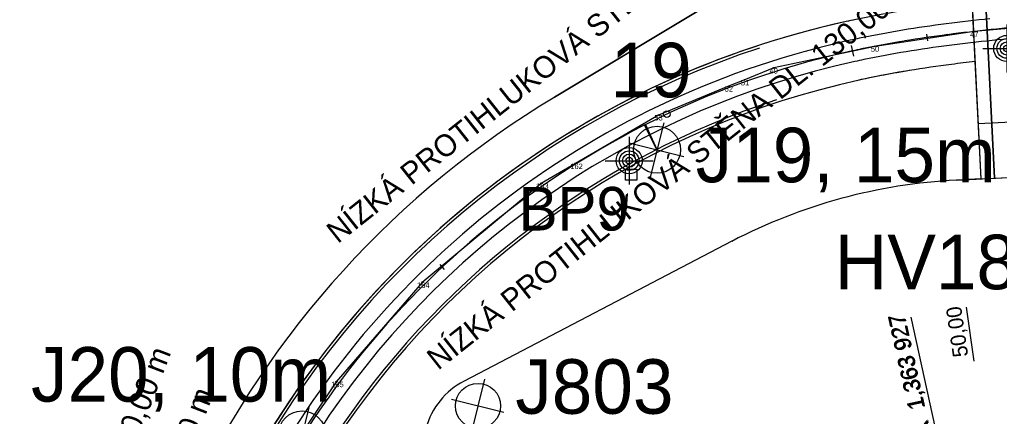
# Model space of a CAD drawing. Extents: x -606444 to -604546, y -1158114 to -1156869.
# Drawn here: x -606212 to -606032.4, y -1157373.9 to -1157301.1 of the extents above; entities that cross this region are included whole.
import ezdxf

# ---------------------------------------------------------------- set-up
doc = ezdxf.new("R2010")
doc.units = 0
for name, color, linetype in [('0_sondy', 7, 'Continuous'), ('ARCHIVNÍ SONDY', 7, 'Continuous'), ('B_CHOD', 7, 'Continuous'), ('B_TRAM', 7, 'Continuous'), ('B_VOZ', 7, 'Continuous'), ('B_ZELEN', 7, 'Continuous'), ('hydrovrty_předběžný GTP', 7, 'Continuous'), ('jádrové vrty_předběžný GTP', 7, 'Continuous'), ('korozní průzkum', 7, 'Continuous'), ('netisk', 7, 'Continuous'), ('netisk2', 7, 'Continuous'), ('NS_VB', 7, 'Continuous'), ('NS_VB_OBJ', 7, 'Continuous'), ('NS_VB_POP', 7, 'Continuous'), ('OSA', 7, 'Continuous'), ('OSAPOP', 7, 'Continuous'), ('podélný profil trasou tramvaje', 7, 'Continuous'), ('sondy předběžného průzkumu', 7, 'Continuous'), ('sondy současného průzkumu', 7, 'Continuous')]:
    doc.layers.add(name, color=color, linetype=linetype)

# ---------------------------------------------------------------- blocks, each defined once
blk = doc.blocks.new('709')
for p, q in [((0, 2.2), (0, -2.2)), ((-2.2, 0), (2.2, 0))]:
    blk.add_line(p, q)
for radius in [1.2, 0.9, 0.6, 0.3]:
    blk.add_circle((0, 0), radius)
blk = doc.blocks.new('IG vrt podr')
at = {"layer": 'sondy současného průzkumu'}
for p, q in [((0.412, 1.649), (-0.418, -1.672)), ((-1.698, 0.422), (1.644, -0.408))]:
    blk.add_line(p, q, dxfattribs=at)
blk.add_circle((-0.002, 0.001), 1.434, dxfattribs=at)
blk = doc.blocks.new('IG vrt archivní')
at = {"layer": 'sondy předběžného průzkumu'}
for p, q in [((0.406, 1.636), (-0.393, -1.584)), ((1.589, -0.397), (-1.612, 0.402))]:
    blk.add_line(p, q, dxfattribs=at)
blk.add_circle((0.001, 0.002), 1.382, dxfattribs=at)

msp = doc.modelspace()

# ---------------------------------------------------------------- linework, layer by layer
for p, q in [((-606037.05, -1157303.31), (-606037.15, -1157303.21)), ((-606037.05, -1157303.31), (-606037.15, -1157303.41)), ((-606037.05, -1157303.31), (-606036.95, -1157303.21)), ((-606037.05, -1157303.31), (-606036.95, -1157303.41)), ((-606055.2, -1157306.01), (-606055.3, -1157305.91)), ((-606055.2, -1157306.01), (-606055.3, -1157306.11)), ((-606055.2, -1157306.01), (-606055.1, -1157305.91)), ((-606055.2, -1157306.01), (-606055.1, -1157306.11)), ((-606073.8, -1157310), (-606073.9, -1157309.9)), ((-606073.8, -1157310), (-606073.9, -1157310.1)), ((-606073.8, -1157310), (-606073.7, -1157309.9)), ((-606073.8, -1157310), (-606073.7, -1157310.1)), ((-606079.19, -1157312.18), (-606079.29, -1157312.08)), ((-606079.19, -1157312.18), (-606079.29, -1157312.28)), ((-606079.19, -1157312.18), (-606079.09, -1157312.08)), ((-606079.19, -1157312.18), (-606079.09, -1157312.28)), ((-606082.05, -1157313.33), (-606082.15, -1157313.23)), ((-606082.05, -1157313.33), (-606082.15, -1157313.43)), ((-606082.05, -1157313.33), (-606081.95, -1157313.23)), ((-606082.05, -1157313.33), (-606081.95, -1157313.43)), ((-606094.93, -1157318.61), (-606095.03, -1157318.51)), ((-606094.93, -1157318.61), (-606095.03, -1157318.71)), ((-606094.93, -1157318.61), (-606094.83, -1157318.51)), ((-606094.93, -1157318.61), (-606094.83, -1157318.71)), ((-606095.17, -1157324.99), (-606095.27, -1157324.89)), ((-606095.17, -1157324.99), (-606095.07, -1157324.89)), ((-606095.17, -1157324.99), (-606095.27, -1157325.09)), ((-606095.17, -1157324.99), (-606095.07, -1157325.09)), ((-606110.15, -1157327.53), (-606110.25, -1157327.43)), ((-606110.15, -1157327.53), (-606110.25, -1157327.63)), ((-606110.15, -1157327.53), (-606110.05, -1157327.43)), ((-606110.15, -1157327.53), (-606110.05, -1157327.63)), ((-606116.44, -1157331.17), (-606116.54, -1157331.07)), ((-606116.44, -1157331.17), (-606116.54, -1157331.27)), ((-606116.44, -1157331.17), (-606116.34, -1157331.07)), ((-606116.44, -1157331.17), (-606116.34, -1157331.27)), ((-606138.24, -1157349.34), (-606138.34, -1157349.24)), ((-606138.24, -1157349.34), (-606138.34, -1157349.44)), ((-606138.24, -1157349.34), (-606138.14, -1157349.24)), ((-606138.24, -1157349.34), (-606138.14, -1157349.44)), ((-606153.99, -1157367.55), (-606154.09, -1157367.45)), ((-606153.99, -1157367.55), (-606154.09, -1157367.65)), ((-606153.99, -1157367.55), (-606153.89, -1157367.45)), ((-606153.99, -1157367.55), (-606153.89, -1157367.65))]:
    msp.add_line(p, q)
at = {"layer": 'B_CHOD'}
for p, q in [((-606038.86, -1157270.13), (-606035.78, -1157330.33)), ((-606033.28, -1157330.2), (-606036.36, -1157270)), ((-606035.78, -1157330.33), (-606033.28, -1157330.2))]:
    msp.add_line(p, q, dxfattribs=at)
at = {"layer": 'B_TRAM'}
msp.add_lwpolyline([(-606037.44, -1157297.79), (-606036.88, -1157308.8)], dxfattribs=at)
for centre, radius, start, end in [((-606024.98, -1157463.17), 165.56, 102.3924, 154.3928), ((-606024.29, -1157466.37), 168.83, 101.7883, 102.3854), ((-606018.68, -1157494.74), 186.75, 99.3179, 101.6987), ((-606012.94, -1157529.72), 222.2, 97.3026, 99.3179), ((-605996.49, -1157658.03), 351.56, 96.5967, 97.3026), ((-606025, -1157463.12), 154.5, 102.3876, 145.5388), ((-606032.02, -1157430.27), 120.92, 101.6987, 102.4763)]:
    msp.add_arc(centre, radius, start, end, dxfattribs=at)
at = {"layer": 'B_VOZ'}
for p, q in [((-606036.36, -1157270), (-606033.28, -1157330.2)), ((-606033.28, -1157330.2), (-606027.29, -1157329.89))]:
    msp.add_line(p, q, dxfattribs=at)
at = {"layer": 'B_ZELEN'}
for points in [[(-606113.95, -1157315.31), (-606038.86, -1157270.13), (-606037.44, -1157297.79)], [(-606036.88, -1157308.8), (-606035.78, -1157330.33), (-606040.29, -1157330.56)], [(-606081.48, -1157341.79), (-606130.56, -1157367.43)]]:
    msp.add_lwpolyline(points, dxfattribs=at)
for centre, radius, start, end in [((-606020.21, -1157486.26), 189.13, 99.2721, 102.3012), ((-606025, -1157463.12), 165.5, 102.3874, 151.5505), ((-606020.21, -1157486.27), 178.14, 99.2721, 102.2958), ((-606011.41, -1157540.2), 232.79, 97.3485, 99.2721), ((-605999.21, -1157634.73), 328.1, 96.5921, 97.3485), ((-606025, -1157463.12), 154.5, 102.3875, 145.5388), ((-606025, -1157463.12), 172.5, 121.038, 154.4605), ((-606035.18, -1157430.43), 100, 92.9282, 117.5817), ((-606124.1, -1157379.8), 13.95, 117.5817, 164.5679)]:
    msp.add_arc(centre, radius, start, end, dxfattribs=at)
at = {"layer": 'korozní průzkum'}
msp.add_lwpolyline([(-606100.93, -1157328.56), (-606098.85, -1157328.56), (-606098.85, -1157330.59), (-606100.93, -1157330.59)], close=True, dxfattribs=at)
at = {"layer": 'netisk'}
msp.add_line((-606097.36, -1157320.2), (-606095.17, -1157325.06), dxfattribs=at)
at = {"layer": 'netisk2'}
msp.add_line((-606095.17, -1157325.06), (-606097.5, -1157320.48), dxfattribs=at)
at = {"layer": 'NS_VB'}
for p, q in [((-606038.86, -1157270.13), (-606113.95, -1157315.31)), ((-606038.86, -1157270.13), (-606035.78, -1157330.33)), ((-606036.36, -1157270), (-606033.28, -1157330.2)), ((-606040.29, -1157330.56), (-606024.79, -1157329.76)), ((-606081.48, -1157341.79), (-606130.56, -1157367.43))]:
    msp.add_line(p, q, dxfattribs=at)
for centre, radius, start, end in [((-606025, -1157463.12), 165.5, 102.3874, 151.5505), ((-606024.29, -1157466.37), 168.83, 101.7883, 102.3854), ((-606019.94, -1157487.94), 179.83, 99.2721, 101.7446), ((-606011.41, -1157540.2), 232.79, 97.3485, 99.2721), ((-605999.21, -1157634.73), 328.1, 96.5921, 97.3485), ((-606025, -1157463.12), 154.5, 102.3875, 145.5388), ((-606024.29, -1157466.37), 157.83, 101.7898, 102.3853), ((-606025, -1157463.12), 172.5, 121.038, 154.4605), ((-606035.18, -1157430.43), 100, 92.9282, 117.5817), ((-606124.1, -1157379.8), 13.95, 117.5817, 164.5679)]:
    msp.add_arc(centre, radius, start, end, dxfattribs=at)
at = {"layer": 'NS_VB_OBJ'}
msp.add_lwpolyline([(-606036.3, -1157320.19), (-606025.31, -1157319.63)], dxfattribs=at)
for radius, end in [(165, 151.5504), (155, 145.5388)]:
    msp.add_arc((-606025, -1157463.12), radius, 108.142, end, dxfattribs=at)
at = {"layer": 'OSA'}
for centre, radius, start, end in [((-605999.21, -1157634.73), 335.6, 95.9745, 97.3485), ((-606019.94, -1157487.94), 187.33, 99.2721, 101.7455), ((-606011.41, -1157540.2), 240.29, 97.3485, 99.2721), ((-605999.21, -1157634.73), 333.6, 95.9745, 97.3485), ((-605976.07, -1157855.92), 556, 95.1501, 95.9745), ((-606025, -1157463.12), 162, 102.3874, 151.55), ((-606024.29, -1157466.37), 165.33, 101.7887, 102.3854), ((-606019.94, -1157487.94), 185.33, 99.2721, 101.7453), ((-606011.41, -1157540.2), 238.29, 97.3485, 99.2721), ((-605999.21, -1157634.73), 331.6, 95.9745, 97.3485), ((-605976.07, -1157855.92), 554, 95.1501, 95.9745), ((-606025, -1157463.12), 160, 102.3874, 151.5497), ((-606024.29, -1157466.37), 163.33, 101.789, 102.3854), ((-606011.41, -1157540.2), 236.29, 97.3485, 99.2721), ((-606024.29, -1157466.37), 161.33, 101.7893, 102.3853), ((-606019.94, -1157487.94), 183.33, 99.2721, 101.745), ((-606025, -1157463.12), 158, 102.3874, 145.5388), ((-606109.93, -1157404.83), 55, 145.5388, 194.4799)]:
    msp.add_arc(centre, radius, start, end, dxfattribs=at)
at = {"layer": 'OSAPOP'}
for p, q in [((-606045.54, -1157304.98), (-606045.71, -1157303.79)), ((-606059.11, -1157307.82), (-606059.54, -1157305.86)), ((-606134.14, -1157346.94), (-606134.96, -1157346.06)), ((-606037.03, -1157363.76), (-606038.46, -1157353.87)), ((-606043.24, -1157380.09), (-606048.6, -1157355.68))]:
    msp.add_line(p, q, dxfattribs=at)
msp.add_circle((-606093.39, -1157318.47), 0.6, dxfattribs=at)
at = {"layer": 'podélný profil trasou tramvaje'}
msp.add_lwpolyline([(-605949.82, -1157295.6), (-605999.99, -1157299.9), (-606029.31, -1157302.59), (-606037.05, -1157303.31), (-606055.2, -1157306.01), (-606073.75, -1157309.95), (-606079.24, -1157312.23), (-606082.05, -1157313.33), (-606094.93, -1157318.61), (-606110.15, -1157327.53), (-606116.44, -1157331.17), (-606138.24, -1157349.34), (-606153.99, -1157367.55), (-606162.8, -1157380.7), (-606171.56, -1157397.75), (-606180.53, -1157420.69), (-606192.65, -1157452.3), (-606195.21, -1157458.76), (-606195.21, -1157458.76), (-606195.33, -1157460.2), (-606196.07, -1157462.31), (-606197.75, -1157467.6), (-606193.13, -1157485.08)], dxfattribs=at)

# ---------------------------------------------------------------- block references
at = {"layer": '0_sondy', "xscale": 2, "yscale": 2}
for p in [(-606031.05, -1157306.4), (-606100.28, -1157326.99)]:
    msp.add_blockref('709', p, dxfattribs=at)
at = {"layer": 'ARCHIVNÍ SONDY', "xscale": 3, "yscale": 3}
msp.add_blockref('IG vrt archivní', (-606128, -1157372), dxfattribs=at)
at = {"layer": 'jádrové vrty_předběžný GTP', "xscale": 3, "yscale": 3}
for p in [(-606095.17, -1157324.99), (-606160.25, -1157377.21)]:
    msp.add_blockref('IG vrt podr', p, dxfattribs=at)

# ---------------------------------------------------------------- texts
for s, p in [('47', (-606037.78, -1157304.31)), ('50', (-606055.97, -1157307.01)), ('49', (-606074.54, -1157311)), ('51', (-606079.81, -1157313.18)), ('52', (-606082.78, -1157314.33)), ('53', (-606095.66, -1157319.61)), ('162', (-606111.08, -1157328.53)), ('163', (-606117.37, -1157332.17)), ('164', (-606139.17, -1157350.34)), ('165', (-606154.92, -1157368.55))]:
    msp.add_text(s, height=1).set_placement(p)
at = {"layer": '0_sondy'}
msp.add_text('19', height=10, dxfattribs=at).set_placement((-606103.7, -1157315.36))
at = {"layer": 'ARCHIVNÍ SONDY'}
msp.add_text('J803', height=10, dxfattribs=at).set_placement((-606121.16, -1157373.43))
at = {"layer": 'hydrovrty_předběžný GTP'}
msp.add_text('HV18,15m', height=10, dxfattribs=at).set_placement((-606062.62, -1157350.58))
at = {"layer": 'jádrové vrty_předběžný GTP'}
for s, p in [('J19, 15m', (-606088.08, -1157330.95)), ('J20, 10m', (-606209.94, -1157371.2))]:
    msp.add_text(s, height=10, dxfattribs=at).set_placement(p)
at = {"layer": 'korozní průzkum'}
msp.add_text('BP9', height=8, dxfattribs=at).set_placement((-606120.54, -1157339.81))
at = {"layer": 'NS_VB_POP'}
for s, rotation, p in [('NÍZKÁ PROTIHLUKOVÁ STĚNA DL. 140,00 m', 38.3478, (-606153.71, -1157342.32)), ('NÍZKÁ PROTIHLUKOVÁ STĚNA DL. 130,00 m', 38.3478, (-606135.32, -1157365.56)), ('OPĚRNÁ ZEĎ DL. 120,00 m', 69.0161, (-606208.69, -1157425.98)), ('NÁSTUPIŠTĚ DL. 44,00 m', 69.0161, (-606199.35, -1157429.56))]:
    msp.add_text(s, height=4, rotation=rotation, dxfattribs=at).set_placement(p)
at = {"layer": 'OSAPOP'}
for s, height, rotation, p in [('50,00', 2.8, 98.2331, (-606038.11, -1157362.83)), ('PK  1,363 927', 3, 102.3874, (-606044.51, -1157379.66)), ('PK  1,363 927', 3, 102.3874, (-606044.33, -1157379.77))]:
    msp.add_text(s, height=height, rotation=rotation, dxfattribs=at).set_placement(p)

doc.saveas('drawing.dxf')
